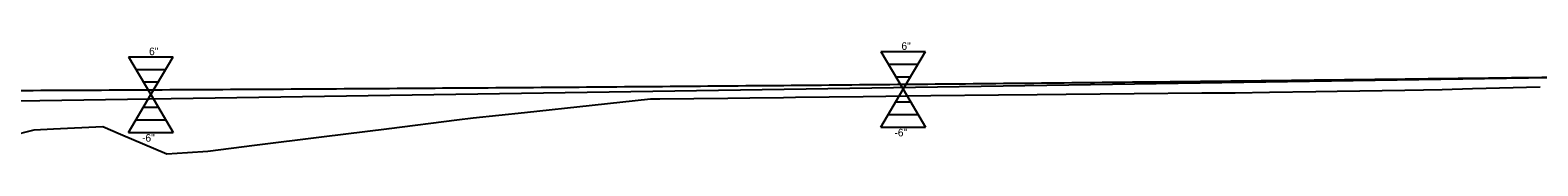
# Model space of a CAD drawing. Extents: x 573468 to 580768, y -57414 to -51768.
# Drawn here: x 575698.2 to 575797.7, y -53385.4 to -53378.1 of the extents above; entities that cross this region are included whole.
import ezdxf

# ---------------------------------------------------------------- set-up
doc = ezdxf.new("R2010")
doc.units = 0
for name, color, linetype in [('Exist Vertical Profile Ground Line', 7, 'Continuous'), ('Pattern 2', 7, 'Continuous'), ('Prop Vertical Profile Grade', 7, 'Continuous'), ('Prop VPI Label', 7, 'Continuous')]:
    doc.layers.add(name, color=color, linetype=linetype)

msp = doc.modelspace()

# ---------------------------------------------------------------- linework, layer by layer
at = {"layer": 'Exist Vertical Profile Ground Line'}
for points in [[(575698.476, -53383.831), (575699.761, -53383.772), (575703.017, -53383.62), (575704.179, -53384.119), (575707.229, -53385.423), (575708.597, -53385.333), (575709.944, -53385.241), (575713.015, -53384.861), (575717.433, -53384.306), (575721.9, -53383.744), (575726.367, -53383.192), (575727.453, -53383.06), (575730.834, -53382.701), (575735.301, -53382.213), (575739.137, -53381.802), (575739.767, -53381.796), (575744.234, -53381.75), (575745.704, -53381.735), (575747.915, -53381.708), (575748.701, -53381.697), (575750.933, -53381.666), (575753.168, -53381.638), (575757.635, -53381.585), (575762.102, -53381.533), (575764.638, -53381.504), (575766.569, -53381.487), (575771.036, -53381.448), (575775.503, -53381.411), (575777.707, -53381.394), (575779.97, -53381.358), (575783.027, -53381.311), (575784.436, -53381.288), (575788.903, -53381.214), (575791.365, -53381.174), (575793.37, -53381.119), (575797.837, -53380.998)], [(575695.343, -53384.639), (575698.476, -53383.831)]]:
    msp.add_lwpolyline(points, dxfattribs=at)
at = {"layer": 'Pattern 2'}
for p, q in [((575754.341, -53378.668), (575757.274, -53378.668)), ((575754.341, -53378.668), (575755.808, -53381.168)), ((575755.808, -53381.168), (575757.274, -53378.668)), ((575704.711, -53379.018), (575707.644, -53379.018)), ((575704.711, -53379.018), (575706.178, -53381.518)), ((575705.2, -53379.852), (575707.155, -53379.852)), ((575706.178, -53381.518), (575707.644, -53379.018)), ((575754.83, -53379.502), (575756.785, -53379.502)), ((575705.689, -53380.685), (575706.666, -53380.685)), ((575755.319, -53380.335), (575756.296, -53380.335)), ((575704.711, -53384.018), (575706.178, -53381.518)), ((575706.178, -53381.518), (575707.644, -53384.018)), ((575754.341, -53383.668), (575755.808, -53381.168)), ((575755.808, -53381.168), (575757.274, -53383.668)), ((575705.689, -53382.352), (575706.666, -53382.352)), ((575754.83, -53382.835), (575756.785, -53382.835)), ((575755.319, -53382.002), (575756.296, -53382.002)), ((575705.2, -53383.185), (575707.155, -53383.185)), ((575754.341, -53383.668), (575757.274, -53383.668)), ((575704.711, -53384.018), (575707.644, -53384.018))]:
    msp.add_line(p, q, dxfattribs=at)
at = {"layer": 'Prop Vertical Profile Grade'}
msp.add_spline([(575431.428, -53379.651), (575439.428, -53379.781), (575447.428, -53379.906), (575455.428, -53380.026), (575463.428, -53380.141), (575471.428, -53380.251), (575479.428, -53380.356), (575487.428, -53380.455), (575495.428, -53380.55), (575503.428, -53380.639), (575511.428, -53380.723), (575519.428, -53380.802), (575527.428, -53380.876), (575535.428, -53380.945), (575543.428, -53381.009), (575551.428, -53381.068), (575559.428, -53381.121), (575567.428, -53381.17), (575575.428, -53381.213), (575583.428, -53381.251), (575591.428, -53381.285), (575599.428, -53381.313), (575607.428, -53381.336), (575615.428, -53381.353), (575623.428, -53381.366), (575631.428, -53381.374), (575639.428, -53381.376), (575647.428, -53381.374), (575655.428, -53381.366), (575663.428, -53381.353), (575671.428, -53381.335), (575679.428, -53381.312), (575687.428, -53381.284), (575695.428, -53381.251), (575703.428, -53381.212), (575711.428, -53381.169), (575719.428, -53381.12), (575727.428, -53381.067), (575735.428, -53381.008), (575743.428, -53380.944), (575751.428, -53380.875), (575759.428, -53380.801), (575767.428, -53380.722), (575775.428, -53380.637), (575783.428, -53380.548), (575791.428, -53380.453), (575799.428, -53380.354), (575807.428, -53380.249), (575815.428, -53380.139), (575823.428, -53380.024), (575831.428, -53379.904)], degree=3, dxfattribs=at)
at = {"layer": 'Prop VPI Label'}
msp.add_line((575831.428, -53379.904), (575634.177, -53382.928), dxfattribs=at)

# ---------------------------------------------------------------- texts
at = {"layer": 'Pattern 2'}
for s, p in [('6"', (575706.065, -53378.917)), ('6"', (575755.695, -53378.567)), ('-6"', (575755.234, -53384.271)), ('-6"', (575705.604, -53384.621))]:
    msp.add_text(s, height=0.5, rotation=360, dxfattribs=at).set_placement(p)

doc.saveas('drawing.dxf')
